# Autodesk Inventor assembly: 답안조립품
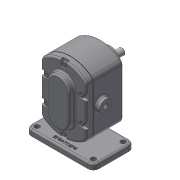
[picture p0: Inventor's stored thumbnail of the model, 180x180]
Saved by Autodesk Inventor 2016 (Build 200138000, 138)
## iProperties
Created: 2019-03
Part Number: 답안조립품
Document SubType Name: Assembly
Designer: 2-PC11
Author: 2-PC11
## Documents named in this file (11)
- C:\Users\2-PC11\Desktop\490308V1001\답안조립품.iam
- C:\Users\2-PC11\Desktop\490308V1001\본체.ipt
- C:\Users\2-PC11\Desktop\490308V1001\메인축.ipt
- C:\Users\2-PC11\Desktop\490308V1001\서브축.ipt
- C:\Users\2-PC11\Desktop\490308V1001\키 6 x 6 x 18.ipt
- C:\Users\2-PC11\Desktop\490308V1001\스퍼기어.ipt
- C:\Users\2-PC11\Desktop\490308V1001\베어링부시.ipt
- C:\Users\2-PC11\Desktop\490308V1001\개스킷.ipt
- C:\Users\2-PC11\Desktop\490308V1001\커버.ipt
- C:\Users\2-PC11\Desktop\490308V1001\볼트 M5.ipt
- C:\Users\2-PC11\Desktop\490308V1001\오일 실 16 28 7.ipt
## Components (1 placed, 1 different names)
1. 개스킷:1
